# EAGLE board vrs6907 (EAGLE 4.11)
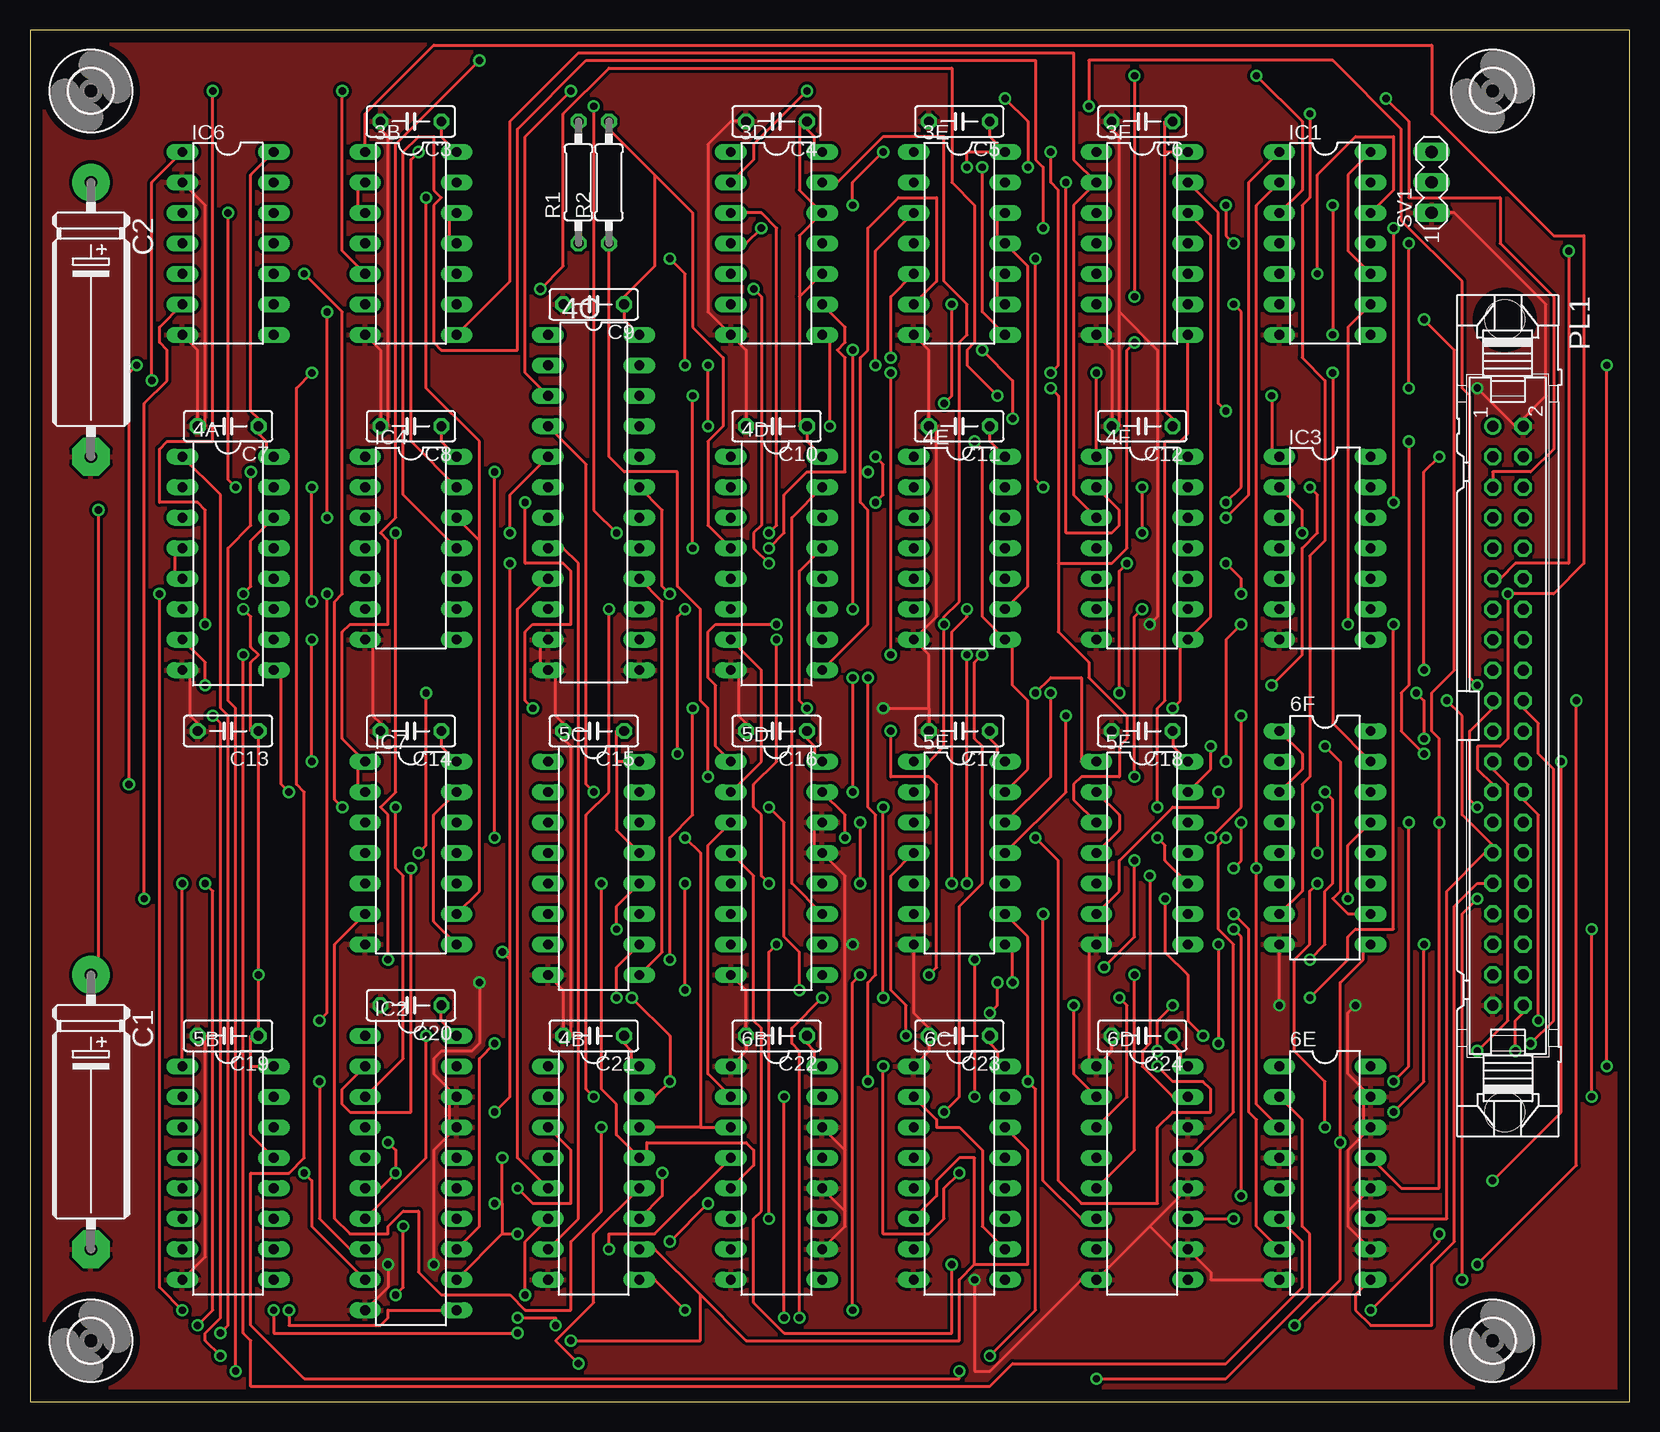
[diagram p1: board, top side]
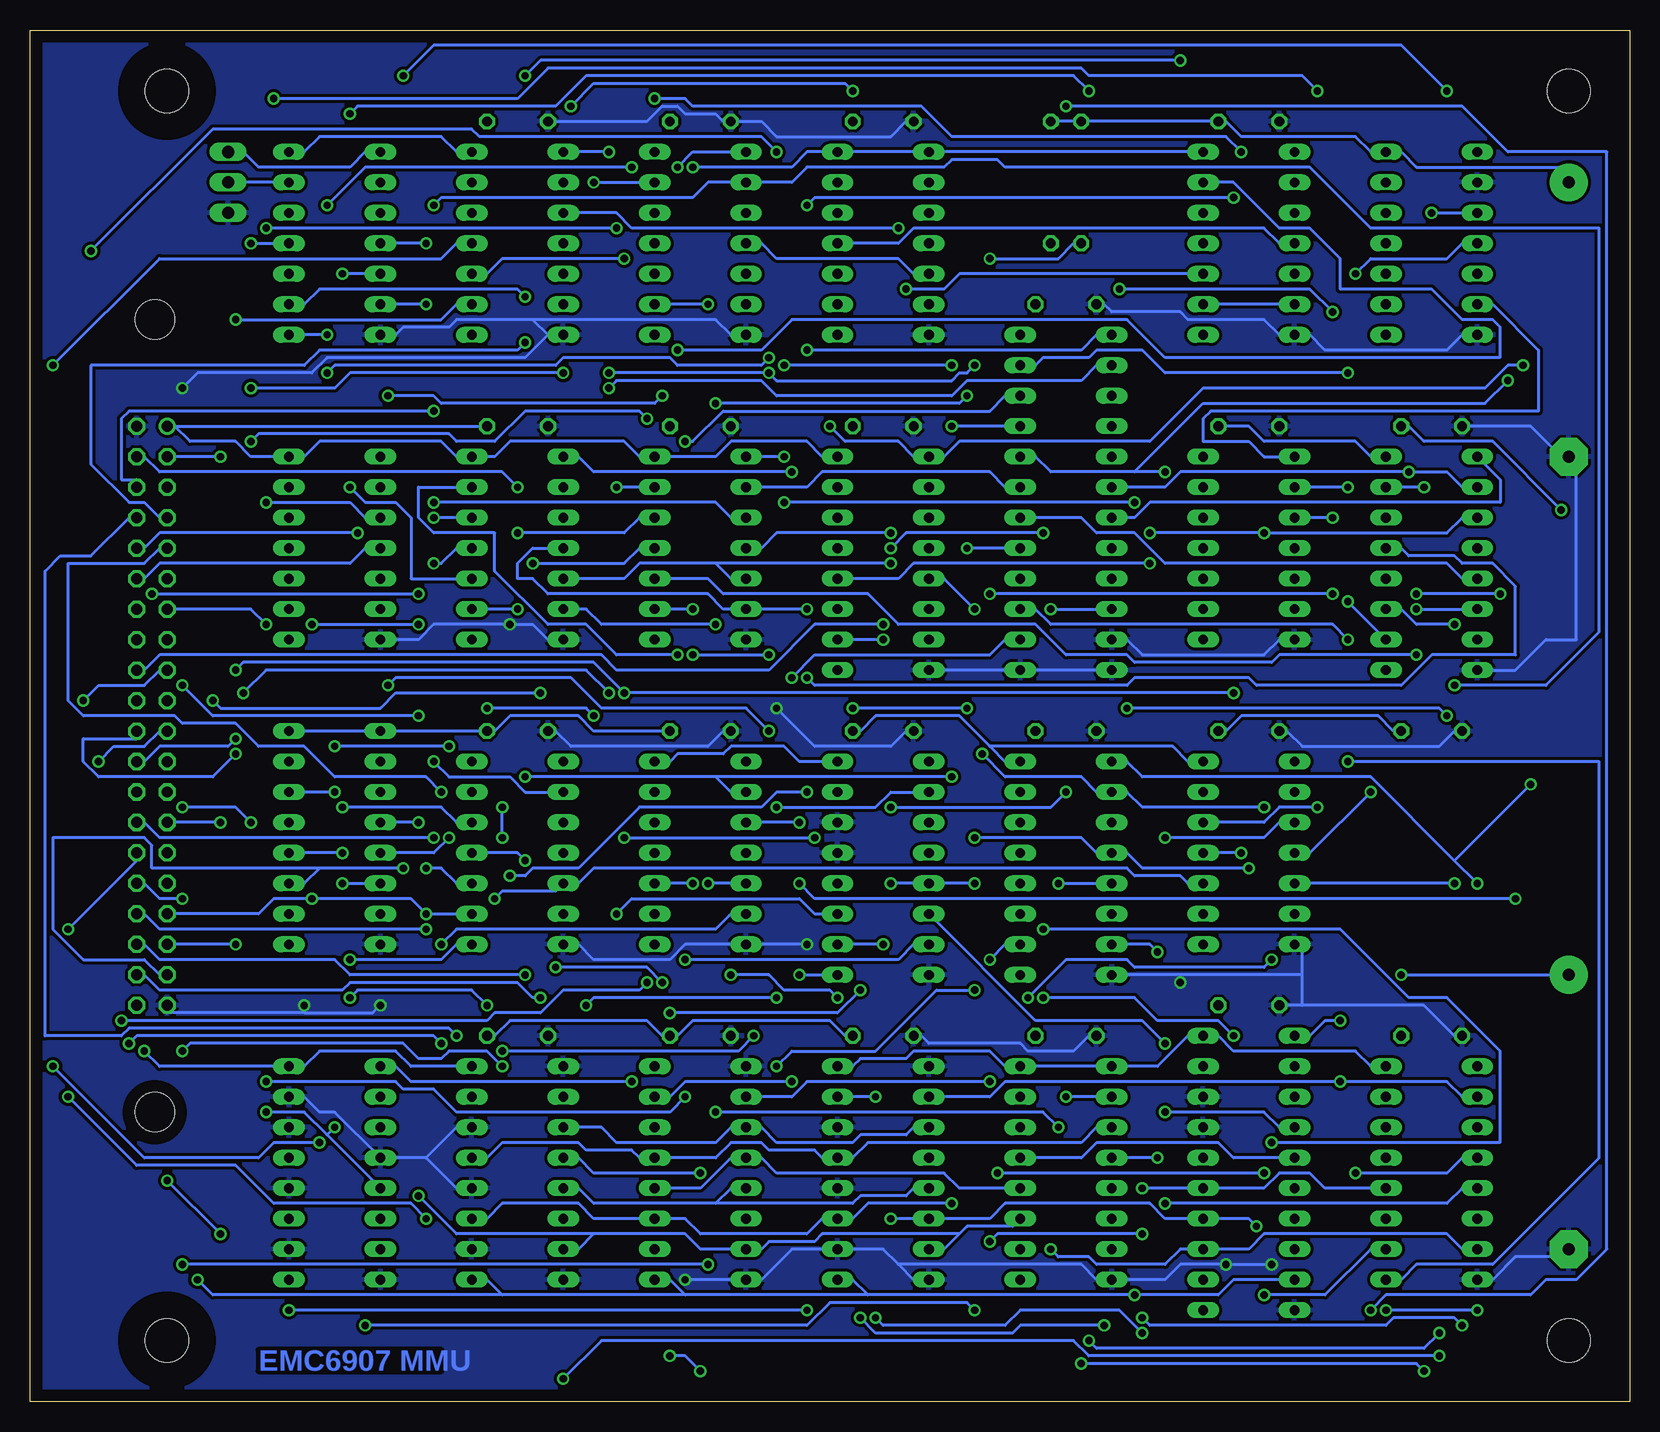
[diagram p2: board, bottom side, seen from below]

Size 133.35 x 114.3 mm. Coordinates in mm from the lower left corner, seen from the top.
Outline: 0,0 133.35,0 133.35,114.3 0,114.3 0,0
Copper layers (1*16): Top 0.035mm / dielectric 1.5mm / Bottom 0.035mm
Design rules "10mils": minimum track width 10mil, minimum drill 24mil, track to track 10mil, track to pad 10mil, pad to pad 10mil, via to via 10mil, smd to smd 10mil, copper to edge 40mil, drill to drill 10mil, minimum pad ring 10mil, minimum via ring 8mil, stop-mask expansion 0mil, vias tented up to drill 0mil, thermal gap 10mil

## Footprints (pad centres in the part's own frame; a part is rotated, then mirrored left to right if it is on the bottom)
DIL14 = drill 0.813 long: 1 -7.62,-3.81; 2 -5.08,-3.81; 3 -2.54,-3.81; 4 0,-3.81; 5 2.54,-3.81; 6 5.08,-3.81; 7 7.62,-3.81; 8 7.62,3.81; 9 5.08,3.81; 10 2.54,3.81; 11 0,3.81; 12 -2.54,3.81; 13 -5.08,3.81; 14 -7.62,3.81
DIL16 = drill 0.813 long: 1 -8.89,-3.81; 2 -6.35,-3.81; 3 -3.81,-3.81; 4 -1.27,-3.81; 5 1.27,-3.81; 6 3.81,-3.81; 7 6.35,-3.81; 8 8.89,-3.81; 9 8.89,3.81; 10 6.35,3.81; 11 3.81,3.81; 12 1.27,3.81; 13 -1.27,3.81; 14 -3.81,3.81; 15 -6.35,3.81; 16 -8.89,3.81
DIL24-3 = drill 0.813 long: 1 -13.97,-3.81; 2 -11.43,-3.81; 3 -8.89,-3.81; 4 -6.35,-3.81; 5 -3.81,-3.81; 6 -1.27,-3.81; 7 1.27,-3.81; 8 3.81,-3.81; 9 6.35,-3.81; 10 8.89,-3.81; 11 11.43,-3.81; 12 13.97,-3.81; 13 13.97,3.81; 14 11.43,3.81; 15 8.89,3.81; 16 6.35,3.81; 17 3.81,3.81; 18 1.27,3.81; 19 -1.27,3.81; 20 -3.81,3.81; 21 -6.35,3.81; 22 -8.89,3.81; 23 -11.43,3.81; 24 -13.97,3.81
E22-6 = drill 1.016 pad 3.15 round: + -11.43,0 | drill 1.016 pad 3.15 octagon: - 11.43,0
C050-025X075 = drill 0.813 octagon: 1 -2.54,0; 2 2.54,0
DIL20 = drill 0.813 long: 1 -11.43,-3.81; 2 -8.89,-3.81; 3 -6.35,-3.81; 4 -3.81,-3.81; 5 -1.27,-3.81; 6 1.27,-3.81; 7 3.81,-3.81; 8 6.35,-3.81; 9 8.89,-3.81; 10 11.43,-3.81; 11 11.43,3.81; 12 8.89,3.81; 13 6.35,3.81; 14 3.81,3.81; 15 1.27,3.81; 16 -1.27,3.81; 17 -3.81,3.81; 18 -6.35,3.81; 19 -8.89,3.81; 20 -11.43,3.81
40V = drill 0.914 round: 1 -24.13,-1.27 | drill 0.914 octagon: 2 -24.13,1.27; 3 -21.59,-1.27; 4 -21.59,1.27; 5 -19.05,-1.27; 6 -19.05,1.27; 7 -16.51,-1.27; 8 -16.51,1.27; 9 -13.97,-1.27; 10 -13.97,1.27; 11 -11.43,-1.27; 12 -11.43,1.27; 13 -8.89,-1.27; 14 -8.89,1.27; 15 -6.35,-1.27; 16 -6.35,1.27; 17 -3.81,-1.27; 18 -3.81,1.27; 19 -1.27,-1.27; 20 -1.27,1.27; 21 1.27,-1.27; 22 1.27,1.27; 23 3.81,-1.27; 24 3.81,1.27; 25 6.35,-1.27; 26 6.35,1.27; 27 8.89,-1.27; 28 8.89,1.27; 29 11.43,-1.27; 30 11.43,1.27; 31 13.97,-1.27; 32 13.97,1.27; 33 16.51,-1.27; 34 16.51,1.27; 35 19.05,-1.27; 36 19.05,1.27; 37 21.59,-1.27; 38 21.59,1.27; 39 24.13,-1.27; 40 24.13,1.27 | hole 3.302: 33.02,-0.254; -33.02,-0.254
0207/10 = drill 0.813 octagon: 1 -5.08,0; 2 5.08,0
MA03-1 = drill 1.016 long: 1 -2.54,0; 2 0,0; 3 2.54,0
3,6 = hole 3.6: 0,0

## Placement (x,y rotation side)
3B  7414N  [DIL14]  31.75,96.52 270 top
3D  74LS74N  [DIL14]  62.23,96.52 270 top
3E  74LS10N  [DIL14]  77.47,96.52 270 top
3F  74LS00N  [DIL14]  92.71,96.52 270 top
4A  74HCT138N  [DIL16]  16.51,69.85 270 top
4B  74LS174N  [DIL16]  46.99,19.05 270 top
4C  20L10  [DIL24-3]  46.99,74.93 270 top
4D  74LS175N  [DIL16]  62.23,69.85 270 top
4E  74LS02N  [DIL14]  77.47,71.12 270 top
4F  74LS04N  [DIL14]  92.71,71.12 270 top
5B  74LS175N  [DIL16]  16.51,19.05 270 top
5C  74LS175N  [DIL16]  46.99,44.45 270 top
5D  74LS257N  [DIL16]  62.23,44.45 270 top
5E  7407N  [DIL14]  77.47,45.72 270 top
5F  74LS32N  [DIL14]  92.71,45.72 270 top
6B  74LS365N  [DIL16]  62.23,19.05 270 top
6C  74LS365N  [DIL16]  77.47,19.05 270 top
6D  74LS365N  [DIL16]  92.71,19.05 270 top
6E  74LS365N  [DIL16]  107.95,19.05 270 top
6F  74LS174N  [DIL16]  107.95,46.99 270 top
C1  27uf  [E22-6]  5.08,24.13 270 top
C2  27uf  [E22-6]  5.08,90.17 270 top
C3  .01uf  [C050-025X075]  31.75,106.68 180 top
C4  .01uf  [C050-025X075]  62.23,106.68 180 top
C5  .01uf  [C050-025X075]  77.47,106.68 180 top
C6  .01uf  [C050-025X075]  92.71,106.68 180 top
C7  .01uf  [C050-025X075]  16.51,81.28 180 top
C8  .01uf  [C050-025X075]  31.75,81.28 180 top
C9  .01uf  [C050-025X075]  46.99,91.44 180 top
C10  .01uf  [C050-025X075]  62.23,81.28 180 top
C11  .01uf  [C050-025X075]  77.47,81.28 180 top
C12  .01uf  [C050-025X075]  92.71,81.28 180 top
C13  .01uf  [C050-025X075]  16.51,55.88 180 top
C14  .01uf  [C050-025X075]  31.75,55.88 180 top
C15  .01uf  [C050-025X075]  46.99,55.88 180 top
C16  .01uf  [C050-025X075]  62.23,55.88 180 top
C17  .01uf  [C050-025X075]  77.47,55.88 180 top
C18  .01uf  [C050-025X075]  92.71,55.88 180 top
C19  .01uf  [C050-025X075]  16.51,30.48 180 top
C20  .01uf  [C050-025X075]  31.75,33.02 180 top
C21  .01uf  [C050-025X075]  46.99,30.48 180 top
C22  .01uf  [C050-025X075]  62.23,30.48 180 top
C23  .01uf  [C050-025X075]  77.47,30.48 180 top
C24  .01uf  [C050-025X075]  92.71,30.48 180 top
IC1  74LS74N  [DIL14]  107.95,96.52 270 top
IC2  74HCT374N  [DIL20]  31.75,19.05 270 top
IC3  7407N  [DIL14]  107.95,71.12 270 top
IC4  74LS32N  [DIL14]  31.75,71.12 270 top
IC6  74LS74N  [DIL14]  16.51,96.52 270 top
IC7  74LS10N  [DIL14]  31.75,45.72 270 top
PL1  [40V]  123.19,57.15 270 top
R1  [0207/10]  45.72,101.6 90 top
R2  [0207/10]  48.26,101.6 90 top
SV1  [MA03-1]  116.84,101.6 90 top
U$1  [3,6]  5.08,109.22 0 top
U$2  [3,6]  121.92,109.22 0 top
U$3  [3,6]  5.08,5.08 0 top
U$4  [3,6]  121.92,5.08 0 top

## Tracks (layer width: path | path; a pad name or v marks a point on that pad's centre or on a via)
2X4\
  Top 0.254: 4A.5 12.06,69.22 12.06,70.48 4A.4
  Bottom 0.254: 4C.18 45.72,73.66 44.45,72.39 41.27,72.39 38.73,69.85 15.24,69.85 13.97,68.58 4A.5
ANYJ  (via drill 0.61)
  Top 0.254: v98.42,46.99 100.97,49.53 v100.97,57.15 | v120.65,59.69 120.02,60.33 120.02,83.82 119.38,84.45 119.38,93.34 114.3,98.42 114.3,106.05 108.58,111.76 88.27,111.76 v88.27,107.95 | v64.77,109.22 60.33,104.78 60.33,103.5 3D.2
  Bottom 0.254: v98.42,46.99 99.69,45.72 6F.5 | v100.97,57.15 118.11,57.15 v120.65,59.69 | v88.27,107.95 86.36,109.86 65.41,109.86 v64.77,109.22
C0\  (via drill 0.61)
  Top 0.254: v85.09,59.05 85.09,52.07 5E.12 | v115.57,59.05 116.2,58.42 v116.2,55.24
  Bottom 0.254: v85.09,59.05 87,60.96 113.67,60.96 v115.57,59.05 | v116.2,55.24 116.84,54.61 122.56,54.61 123.83,53.34 PL1.24
C1\  (via drill 0.61)
  Top 0.254: v81.92,34.92 81.92,37.47 5E.8 | v125.73,31.75 125.73,48.9 124.46,50.16 PL1.26
  Bottom 0.254: v81.92,34.92 82.55,34.29 88.9,34.29 90.81,32.38 94.61,32.38 95.25,31.75 v125.73,31.75
CINT\  (via drill 0.61)
  Top 0.254: v17.14,76.2 16.51,76.83 v16.51,99.06
  Bottom 0.254: v17.14,76.2 4A.15 | v16.51,99.06 IC6.3
CLKDF  (via drill 0.61)
  Top 0.254: v23.5,53.34 v23.5,63.5
  Bottom 0.254: v23.5,53.34 2.54,53.34 2.54,20.32 11.43,11.43 17.78,11.43 19.05,10.16 5B.9 | v23.5,63.5 24.77,64.77 48.26,64.77 49.53,66.04 4C.15
CLKIB
  Top 0.254: 5C.9 52.7,37.47 52.7,66.67 4C.16
CLKIF  (via drill 0.61)
  Top 0.254: v56.52,81.28 v56.52,86.36 | v70.48,86.36 70.48,95.89 3E.3
  Bottom 0.254: v56.52,86.36 v70.48,86.36 | 4C.21 v56.52,81.28
CPUDEVSEL\  (via drill 0.61)
  Top 0.254: v32.38,45.72 33.02,46.35 v33.02,59.05 | v83.82,59.05 85.09,60.33 87.63,60.33 87.63,53.34 5F.1 | v117.47,78.74 116.2,77.47 v116.2,60.96
  Bottom 0.254: v33.02,59.05 v83.82,59.05 86.36,61.59 115.57,61.59 v116.2,60.96 | v32.38,45.72 IC7.11 | v117.47,78.74 PL1.3
CPUSWSEL\  (via drill 0.61)
  Top 0.254: v97.79,30.48 96.52,31.75 96.52,35.56 94.61,37.47 v94.61,41.91
  Bottom 0.254: IC7.10 36.83,43.18 37.47,43.81 41.27,43.81 41.91,44.45 86.36,44.45 87.63,43.18 5F.5 89.53,42.55 93.98,42.55 v94.61,41.91 | v97.79,30.48 98.42,31.11 125.09,31.11 125.73,30.48 132.08,30.48 132.08,69.22 130.81,70.48 128.27,70.48 125.09,73.66 PL1.8
CUF\  (via drill 0.61)
  Top 0.254: v21.59,50.8 20.95,51.44 20.95,60.33 4A.9
  Bottom 0.254: v21.59,50.8 26.67,45.72 IC7.4
DATAF  (via drill 0.61)
  Top 0.254: v62.23,64.77 57.15,64.77 56.52,64.14 56.52,60.33 57.15,59.69 57.15,54.61 5D.1
  Bottom 0.254: v62.23,64.77 67.94,64.77 71.75,60.96 84.45,60.96 85.72,62.23 122.56,62.23 123.83,60.96 PL1.18
DEVSEL\  (via drill 0.61)
  Top 0.254: 85.72,69.85 85.72,83.82 v85.09,84.45 | 85.72,69.85 85.72,64.14 88.27,61.59 88.27,60.33 91.44,57.15 91.44,55.24 90.81,54.61 90.81,52.07 87.63,52.07 87,51.44 87,50.16 5F.3 | v92.08,88.27 91.44,87.63 91.44,71.12 90.17,69.85 85.72,69.85
  Bottom 0.254: v85.09,84.45 84.45,85.09 72.39,85.09 71.12,83.82 56.52,83.82 55.24,85.09 45.72,85.09 44.45,86.36 4C.2 | v92.08,88.27 92.71,87.63 109.22,87.63 110.49,86.36 128.27,86.36 128.27,78.11 125.09,74.93 123.83,74.93 122.56,73.66 PL1.7
DIRJ  (via drill 0.61)
  Top 0.254: v108.58,85.72 108.58,56.52 6F.15 | v71.75,87 71.75,92.08 3E.5
  Bottom 0.254: v108.58,85.72 107.95,86.36 89.53,86.36 88.9,87 80.01,87 79.38,86.36 72.39,86.36 v71.75,87
DMAGNT  (via drill 0.61)
  Top 0.254: v67.94,46.99 67.94,48.9 5D.15 | v83.82,46.99 85.72,45.09 85.72,18.41 87.63,16.51 93.98,16.51 93.98,22.86 95.25,24.13 98.42,24.13 98.42,26.04 97.79,26.67 95.25,26.67 v93.98,27.94 | v120.65,29.21 123.19,31.75 123.19,51.44 121.92,52.7 PL1.23
  Bottom 0.254: v83.82,46.99 v67.94,46.99 | v93.98,27.94 95.25,29.21 98.42,29.21 99.06,28.57 100.97,28.57 102.23,29.84 120.02,29.84 v120.65,29.21
DX0  (via drill 0.61)
  Top 0.254: 6E.13 114.3,17.78 117.47,17.78 v117.47,48.26 117.47,55.24 116.84,55.88 116.84,59.05 118.75,60.96 118.75,87.63 v116.2,90.17
  Bottom 0.254: v117.47,48.26 PL1.27 | v116.2,90.17 99.06,90.17 97.79,91.44 3F.9
DX1  (via drill 0.61)
  Top 0.254: v91.44,69.85 90.81,69.22 v90.81,59.05 | v118.11,58.42 119.38,57.15 119.38,48.9 121.92,46.35 PL1.29 121.28,45.72 118.11,42.55 118.11,15.24 6E.11
  Bottom 0.254: v91.44,69.85 83.82,69.85 82.55,71.12 4E.11 | v90.81,59.05 102.87,59.05 104.14,57.78 117.47,57.78 v118.11,58.42
DX2
  Top 0.254: 6E.9 110.49,8.89 110.49,7.62 111.76,6.35 116.84,6.35 116.84,11.43 118.75,13.34 118.75,41.27 120.65,43.18 PL1.31
DX3  (via drill 0.61)
  Top 0.254: v100.33,40.64 101.6,39.37 101.6,24.13 102.23,23.5 102.23,14.61 6E.7 | v109.86,41.91 109.86,46.35 6F.13
  Bottom 0.254: 5F.9 v100.33,40.64 101.6,41.91 v109.86,41.91 113.03,41.91 114.3,40.64 PL1.33
DX4  (via drill 0.61)
  Top 0.254: v113.67,24.13 116.2,26.67 v116.2,38.1 | v107.31,43.18 106.68,42.55 106.68,38.1 105.41,36.83 105.41,29.21 107.95,26.67 v107.95,22.86
  Bottom 0.254: 108.58,22.23 110.49,24.13 v113.67,24.13 | 6E.5 108.58,22.23 | v116.2,38.1 PL1.35 | 108.58,22.23 v107.95,22.86 | v107.31,43.18 6F.6
DX5  (via drill 0.61)
  Top 0.254: 6E.3 102.23,24.77 v102.23,44.45 102.23,99.69 IC1.2
  Bottom 0.254: 109.22,44.45 110.49,43.18 6F.11 | v102.23,44.45 109.22,44.45 | 109.22,44.45 123.19,44.45 123.19,46.35 123.83,46.99 131.44,46.99 131.44,39.37 128.91,36.83 123.83,36.83 122.56,35.56 PL1.37
DX6  (via drill 0.61)
  Top 0.254: v31.75,44.45 31.75,24.13 26.67,24.13 26.04,24.77 26.04,26.04 IC2.2 | 55.88,22.86 4B.14 | 55.88,22.86 6B.3 | v90.81,33.66 91.44,33.02 91.44,25.4 6D.3 | v54.61,46.99 55.88,45.72 55.88,22.86
  Bottom 0.254: v31.75,44.45 40.64,44.45 41.91,45.72 5C.4 44.45,45.72 45.72,46.99 v54.61,46.99 | 6D.3 85.72,22.86 84.45,21.59 76.2,21.59 74.93,22.86 6C.3 72.39,22.86 71.12,21.59 64.77,21.59 64.14,22.23 60.33,22.23 59.69,22.86 6B.3 | v90.81,33.66 91.44,33.66 92.71,34.92 106.68,34.92 107.31,34.29 122.56,34.29 123.83,35.56 PL1.38
DX7  (via drill 0.61)
  Top 0.254: 6B.5 60.33,19.68 60.33,20.95 59.69,21.59 51.44,21.59 51.44,20.95 4B.13 48.9,22.23 48.9,24.77 47.62,26.04 v47.62,43.18 | v92.08,35.56 92.08,20.95 6D.5
  Bottom 0.254: IC2.5 33.02,20.32 34.29,21.59 44.45,21.59 45.72,20.32 4B.13 | v47.62,43.18 5C.5 | 76.2,16.51 74.93,17.78 6C.5 | 76.2,16.51 86.36,16.51 87.63,17.78 6D.5 | v92.08,35.56 106.68,35.56 107.95,36.83 122.56,36.83 123.83,38.1 PL1.36 | 76.2,16.51 64.77,16.51 64.14,17.14 60.33,17.14 59.69,17.78 6B.5
DX8  (via drill 0.61)
  Top 0.254: v52.7,19.05 52.7,17.14 4B.11 | IC2.6 29.21,17.78 v30.48,19.05 30.48,20.95 v29.84,21.59 | v48.9,39.37 48.9,41.27 5C.12 | v100.33,39.37 100.97,38.73 v100.97,17.14
  Bottom 0.254: 55.88,13.97 55.24,14.61 51.44,14.61 4B.11 | 55.88,13.97 57.15,12.7 6B.7 | 55.88,13.97 67.31,13.97 67.94,13.34 71.75,13.34 72.39,12.7 6C.7 77.47,12.7 78.74,13.97 86.36,13.97 | v30.48,19.05 v52.7,19.05 | v48.9,39.37 24.13,39.37 18.41,33.66 15.24,33.66 10.79,29.21 10.79,21.59 v29.84,21.59 | 86.36,13.97 87.63,12.7 6D.7 | v100.33,39.37 122.56,39.37 123.83,40.64 PL1.34 | v100.97,17.14 97.79,13.97 86.36,13.97
DX9  (via drill 0.61)
  Top 0.254: v41.27,8.89 41.27,13.34 4B.6 | v22.86,19.05 23.5,18.41 23.5,14.61 IC2.9 | v120.65,41.91 119.38,40.64 v119.38,10.16
  Bottom 0.254: 63.5,8.89 v41.27,8.89 34.29,8.89 33.02,10.16 IC2.9 | 63.5,8.89 64.77,10.16 6B.9 | 78.74,8.89 80.01,10.16 6C.9 | 63.5,8.89 78.74,8.89 | v22.86,19.05 15.24,19.05 13.97,20.32 5B.4 | 93.98,8.89 95.25,10.16 6D.9 | 78.74,8.89 93.98,8.89 | v120.65,41.91 122.56,41.91 123.83,43.18 PL1.32 | v119.38,10.16 118.11,8.89 93.98,8.89
DX10  (via drill 0.61)
  Top 0.254: 39.37,16.51 v39.37,20.32 | 39.37,16.51 39.37,13.97 | 39.37,13.97 IC2.12 | v38.73,16.51 39.37,16.51 | v130.18,25.4 v130.18,39.37 | 6D.11 v100.33,15.24 | 39.37,13.97 v40.64,13.97 | v53.34,13.34 v56.52,16.51
  Bottom 0.254: v39.37,20.32 4B.4 | v38.73,16.51 15.24,16.51 13.97,17.78 5B.5 | 6D.11 95.25,15.24 93.98,16.51 87.63,16.51 86.36,15.24 6C.11 78.74,15.24 77.47,13.97 68.58,13.97 67.31,15.24 6B.11 64.77,15.24 63.5,16.51 v56.52,16.51 | v130.18,39.37 124.46,45.09 PL1.30 | v130.18,25.4 124.46,19.68 116.2,19.68 113.03,16.51 101.6,16.51 v100.33,15.24 | v40.64,13.97 52.7,13.97 v53.34,13.34
DX11  (via drill 0.61)
  Top 0.254: v40.64,17.78 41.91,16.51 45.09,16.51 45.09,20.95 4B.3 | v99.69,46.99 99.06,46.35 99.06,39.37 100.33,38.1 100.33,24.13 6D.13
  Bottom 0.254: 5B.12 25.4,17.78 26.67,19.05 29.21,19.05 30.48,17.78 IC2.15 v40.64,17.78 | 4B.3 44.45,22.86 45.72,21.59 63.5,21.59 64.77,20.32 6B.13 67.31,20.32 67.94,20.95 71.75,20.95 72.39,21.59 74.93,21.59 76.2,20.32 6C.13 82.55,20.32 83.19,20.95 87,20.95 87.63,21.59 93.98,21.59 95.25,20.32 6D.13 | v99.69,46.99 122.56,46.99 123.83,48.26 PL1.28
EM0  (via drill 0.61)
  Top 0.254: v76.83,11.43 76.83,5.71 62.87,5.71 60.33,8.26 60.33,15.24 60.96,15.88 60.96,31.11 60.33,31.75 60.33,43.81 5D.4 | v120.65,11.43 128.91,19.68 v128.91,58.42
  Bottom 0.254: v76.83,11.43 v120.65,11.43 | v128.91,58.42 127.64,59.69 123.83,59.69 122.56,60.96 PL1.17
EM1  (via drill 0.61)
  Top 0.254: v78.74,36.83 v78.74,25.4 | v113.67,26.67 114.94,27.94 v114.94,48.26 | v120.65,49.53 120.02,50.16 120.02,55.88 121.92,57.78 PL1.19
  Bottom 0.254: v78.74,36.83 60.96,36.83 59.69,38.1 5D.7 | v78.74,25.4 80.01,24.13 97.79,24.13 99.69,26.04 102.23,26.04 102.87,26.67 v113.67,26.67 | v114.94,48.26 116.2,49.53 v120.65,49.53
EM2  (via drill 0.61)
  Top 0.254: v69.22,35.56 68.58,34.92 v68.58,7.62 | v111.76,7.62 117.47,13.34 v117.47,13.97 | v121.92,18.41 127.64,24.13 v127.64,53.34
  Bottom 0.254: v68.58,7.62 v111.76,7.62 | v117.47,13.97 v121.92,18.41 | v127.64,53.34 126.36,54.61 123.83,54.61 122.56,55.88 PL1.21 | v69.22,35.56 5D.9
ENSF\  (via drill 0.61)
  Top 0.254: v24.13,31.75 24.77,32.38 v24.77,67.31 | v53.34,67.31 52.7,67.94 52.7,74.3 4C.19
  Bottom 0.254: v24.13,31.75 25.4,31.75 26.67,30.48 IC2.1 | v24.77,67.31 v53.34,67.31 | 4E.2 68.58,76.2 67.31,77.47 53.34,77.47 52.07,76.2 4C.19
ERROR\  (via drill 0.61)
  Top 0.254: v26.04,49.53 25.4,50.16 25.4,66.67 26.04,67.31 26.04,90.81 v22.86,93.98
  Bottom 0.254: v26.04,49.53 29.21,49.53 30.48,48.26 IC7.12 | v22.86,93.98 21.59,95.25 15.24,95.25 13.97,96.52 IC6.4
GND  (via drill 0.61)
  Top 0.254: v104.14,33.02 6F.8 | 109.86,15.88 109.86,14.61 6E.10 | 109.86,15.88 6E.12 | 109.86,15.88 109.86,20.95 6E.14 111.12,23.5 111.12,24.77 6E.15 109.86,27.3 109.86,32.38 v110.49,33.02 | 93.34,14.61 6D.8 87.63,10.16 80.01,2.54 78.74,2.54 v78.74,10.16 | 93.34,14.61 6D.12 | 93.34,14.61 95.25,12.7 6D.10 98.42,10.79 98.42,10.16 6E.8 | v29.84,11.43 29.84,9.53 IC2.10 | v33.66,11.43 33.66,20.95 IC2.17 34.92,23.5 34.92,24.77 IC2.18 33.66,27.3 33.66,28.57 34.29,29.21 36.83,29.21 37.47,29.84 v37.47,34.92 | 6C.1 74.93,29.21 C23.2 74.93,31.11 73.66,32.38 5E.7 | C24.2 90.17,29.21 6D.1 88.27,28.57 88.27,37.47 5F.7 | 5D.14 65.41,47.62 65.41,46.35 5D.13 67.94,43.81 67.94,38.1 | 67.94,15.88 67.94,14.61 6B.10 | 67.94,15.88 6B.12 | 67.94,15.88 67.94,20.95 | 67.94,20.95 6B.14 | 67.94,20.95 67.94,38.1 | 67.94,38.1 v68.58,38.1 | C10.2 59.69,87.63 3D.7 56.52,90.81 56.52,104.78 58.42,106.68 C4.2 | SV1.1 118.75,99.06 126.36,91.44 126.36,83.82 124.46,81.92 PL1.2 123.83,81.28 v120.65,84.45 | 74.93,57.78 74.93,62.23 4E.7 75.56,65.41 75.56,81.28 C11.2 74.93,87.63 3E.7 | 74.93,57.78 C17.2 | 3F.7 90.17,87.63 C12.2 90.81,81.28 90.81,90.81 | 90.81,90.81 90.81,105.41 90.17,106.05 C6.2 | v93.34,64.77 93.98,65.41 93.98,87.63 90.81,90.81 | IC6.7 13.97,87.63 C7.2 14.61,81.28 14.61,99.69 IC6.2 | 3B.7 29.21,87.63 C8.2 29.84,81.28 29.84,105.41 29.21,106.05 C3.2 | C13.2 13.97,56.52 13.34,57.15 13.34,60.33 4A.8 | C14.2 29.21,56.52 28.57,57.15 28.57,62.87 IC4.7 | C16.2 59.69,56.52 59.05,57.15 59.05,60.33 4D.8 | 4C.11 42.55,62.87 42.55,61.59 4C.12 43.81,60.33 43.81,57.15 44.45,56.52 C15.2 44.45,55.24 45.09,54.61 45.09,30.48 C21.2 44.45,34.29 5C.8
  Top 0.254: 6B.1 59.69,29.21 C22.2 59.69,34.29 5D.8 | 5B.8 14.61,12.06 14.61,30.48 C19.2 | v71.12,57.78 74.93,57.78
  Bottom 0.254: v104.14,33.02 104.78,32.38 110.49,32.38 | 110.49,32.38 121.92,32.38 PL1.39 | 100.33,20.32 97.79,22.86 6D.14 | 100.33,20.32 6E.4 107.95,24.13 109.22,24.13 110.49,25.4 6E.15 | 100.33,20.32 97.79,17.78 6D.12 | v110.49,33.02 110.49,32.38 | v29.84,11.43 v33.66,11.43 37.47,11.43 38.73,10.16 4B.8 44.45,10.16 45.72,11.43 60.96,11.43 | 5F.7 87.63,38.1 86.36,36.83 80.01,36.83 78.74,38.1 5E.7 v68.58,38.1 | 60.96,11.43 62.23,12.7 6B.10 69.85,12.7 72.39,10.16 6C.8 v78.74,10.16 | 60.96,11.43 59.69,10.16 6B.8 | C4.2 60.33,106.68 61.59,105.41 71.12,105.41 72.39,106.68 C5.2 75.56,106.68 76.2,107.31 78.74,107.31 79.38,107.95 80.64,107.95 81.92,106.68 C6.2 | C18.2 89.53,55.88 88.27,54.61 76.83,54.61 75.56,55.88 C17.2 | 4F.7 90.17,63.5 91.44,64.77 v93.34,64.77 99.69,64.77 100.97,63.5 IC3.7 | 91.44,90.17 97.79,90.17 98.42,89.53 102.23,89.53 102.87,88.9 IC1.7 | 91.44,90.17 90.17,88.9 | 91.44,90.17 76.2,90.17 74.93,88.9 3E.7 | v120.65,84.45 119.38,85.72 109.86,85.72 108.58,87 92.08,87 90.17,88.9 | 90.17,88.9 3F.7 | C7.2 8.26,81.28 6.35,79.38 C2.- 4.45,77.47 4.45,63.5 6.99,63.5 9.53,60.96 4A.8 | C9.2 43.81,91.44 43.18,90.81 37.47,90.81 36.83,90.17 30.48,90.17 29.21,88.9 3B.7 26.67,88.9 25.4,87.63 15.24,87.63 13.97,88.9 IC6.7 | C13.2 14.61,55.88 15.88,54.61 27.3,54.61 28.57,55.88 C14.2 | 4C.12 4C.13 4D.8 | IC4.7 29.21,63.5 30.48,62.23 40.64,62.23 41.91,63.5 4C.11 | 5B.8 11.43,10.16 9.53,12.06 6.35,12.06 C1.- | 27.3,33.02 17.14,33.02 14.61,30.48 C19.2 | 27.3,33.02 C20.2 | 27.3,33.02 27.3,35.56 | 27.3,35.56 27.3,37.47 IC7.7 | 27.3,35.56 37.47,35.56 | 37.47,35.56 5C.8 | C22.2 59.05,30.48 58.42,29.84 50.8,29.84 50.16,29.21 46.35,29.21 45.09,30.48 C21.2
  Bottom 0.254: v71.12,57.78 67.94,54.61 61.59,54.61 60.33,55.88 C16.2 | 37.47,35.56 v37.47,34.92
  pour Bottom: 0,0 0,114.3 133.35,114.3 133.35,0
  pour Top: 0,0 0,114.3 133.35,114.3 133.35,0
GTF\  (via drill 0.61)
  Top 0.254: 5E.13 83.19,52.7 83.19,58.42 81.92,59.69 81.92,62.87 4E.8 79.38,65.41 79.38,79.38 v78.74,80.01
  Bottom 0.254: v78.74,80.01 78.11,80.01 75.56,82.55 53.34,82.55 52.07,83.82 4C.22
IFETCH  (via drill 0.61)
  Top 0.254: v79.38,87.63 81.92,85.09 v81.92,81.92 | v114.94,80.01 114.94,59.69 114.3,59.05 114.3,55.88 v116.2,53.98
  Bottom 0.254: v79.38,87.63 72.39,87.63 69.85,90.17 41.91,90.17 38.73,87 10.79,87 10.79,89.53 11.43,90.17 13.97,90.17 16.51,92.71 24.13,92.71 24.13,95.25 26.67,97.79 29.21,97.79 33.02,101.6 3B.13 | v81.92,81.92 82.55,82.55 92.08,82.55 94.61,80.01 97.79,80.01 98.42,80.64 114.3,80.64 v114.94,80.01 | v116.2,53.98 118.11,52.07 127.64,52.07 128.91,53.34 128.91,55.24 124.46,55.24 PL1.22
INHIBIT\  (via drill 0.61)
  Top 0.254: 3E.12 80.64,98.42 80.64,97.16 3E.11 83.19,94.61 83.19,67.94 4E.9 | v76.83,43.18 76.83,64.14 78.11,65.41 v78.11,66.04
  Bottom 0.254: 5E.5 v76.83,43.18 | v78.11,66.04 4E.9
INHSET\  (via drill 0.61)
  Top 0.254: v55.24,71.12 v55.24,83.82 | v76.2,83.19 76.83,83.82 v76.83,91.44 | 3E.10 80.64,93.34 80.64,92.08 3E.9
  Bottom 0.254: v55.24,83.82 55.88,83.19 v76.2,83.19 | 4C.17 v55.24,71.12 | v76.83,91.44 3E.9
INTDIS  (via drill 0.61)
  Top 0.254: v99.06,38.1 v99.06,29.84 | v125.09,29.84 127,31.75 127,52.7 125.73,53.98 125.73,56.52 124.46,57.78 PL1.20
  Bottom 0.254: v99.06,38.1 97.79,39.37 76.2,39.37 74.93,40.64 5E.6 | v99.06,29.84 99.69,30.48 124.46,30.48 v125.09,29.84
INTGNT  (via drill 0.61)
  Top 0.254: v99.69,69.85 100.97,68.58 v100.97,67.31 | PL1.25 121.92,51.44 120.65,52.7 120.65,54.61 122.56,54.61 123.19,55.24 v123.19,67.31 127,67.31 129.54,69.85 129.54,97.16 127,97.16 116.84,107.31 116.84,113.03 33.66,113.03 27.94,107.31 3B.1
  Bottom 0.254: v99.69,69.85 99.06,69.85 97.79,71.12 4F.11 | v123.19,67.31 v100.97,67.31
INTGNT\  (via drill 0.61)
  Top 0.254: v14.61,43.18 15.24,42.55 15.24,7.62 v13.97,6.35 | v40.64,6.99 43.81,6.99 v43.81,6.35 | v64.14,6.99 64.14,29.21 63.5,29.84 63.5,31.11 v66.04,33.66 | v74.93,35.56 75.56,36.2 75.56,51.44 74.93,52.07 71.75,52.07 v71.75,55.88 | v103.5,59.69 106.05,62.23 106.05,71.12 107.31,72.39 107.31,75.56 v106.68,76.2
  Bottom 0.254: v13.97,6.35 14.61,6.99 19.68,6.99 20.32,6.35 40.01,6.35 v40.64,6.99 | v43.81,6.35 50.8,6.35 51.44,5.71 62.87,5.71 v64.14,6.99 | v66.04,33.66 66.67,34.29 70.48,34.29 71.75,35.56 v74.93,35.56 | v71.75,55.88 73.66,57.78 85.72,57.78 88.27,60.33 102.87,60.33 v103.5,59.69 | v106.68,76.2 105.41,74.93 102.87,74.93 101.6,73.66 101.6,68.58 4F.10 | v14.61,43.18 IC7.5
INTREQ\  (via drill 0.61)
  Top 0.254: v73.03,30.48 73.03,33.02 71.75,34.29 71.75,43.81 5E.4 | v93.98,29.21 93.98,31.75 v95.25,33.02 | v106.68,33.66 109.86,36.83 109.86,38.73 110.49,39.37 113.67,39.37 v113.67,64.77
  Bottom 0.254: v73.03,30.48 74.3,29.21 v93.98,29.21 | v95.25,33.02 96.52,34.29 106.05,34.29 v106.68,33.66 | v113.67,64.77 114.94,66.04 PL1.13
IOCLR\  (via drill 0.61)
  Top 0.254: v38.73,46.99 v38.73,77.47 | v10.16,85.09 10.16,101.6 IC6.1
  Bottom 0.254: v38.73,46.99 30.48,46.99 29.21,48.26 IC7.3 | 41.27,77.47 48.26,77.47 49.53,78.74 4C.20 | v38.73,77.47 41.27,77.47 | v10.16,85.09 12.06,83.19 35.56,83.19 41.27,77.47
IR3  (via drill 0.61)
  Top 0.254: v107.31,49.53 v107.31,45.72
  Bottom 0.254: v107.31,49.53 99.06,49.53 97.79,48.26 5F.12 | v107.31,45.72 6F.12
IR4  (via drill 0.61)
  Top 0.254: v106.68,107.31 106.68,100.33 106.05,99.69 106.05,87 107.95,85.09 107.95,71.75 106.68,70.48 106.68,52.07 106.05,51.44 106.05,42.55 6F.7 | v45.09,109.22 41.27,105.41 41.27,85.72 4C.3
  Bottom 0.254: v106.68,107.31 106.05,107.95 89.53,107.95 87,110.49 46.35,110.49 v45.09,109.22
IR5  (via drill 0.61)
  Top 0.254: v98.42,54.61 98.42,52.7 5F.13 | v107.95,54.61 109.22,53.34 109.22,42.55 108.58,41.91 109.86,40.64 6F.10
  Bottom 0.254: v98.42,54.61 v107.95,54.61
IR6  (via drill 0.61)
  Top 0.254: v40.01,72.39 40.01,75.56 4C.5 | 4B.15 52.07,25.4 v53.34,26.67 53.34,30.48 v50.16,33.66 | 6C.10 79.38,14.61 79.38,20.95 77.47,22.86 75.56,22.86 75.56,23.5 6C.2 | v30.48,72.39 30.48,50.8 29.21,49.53 29.84,48.9 v29.84,36.83
  Bottom 0.254: v40.01,72.39 v30.48,72.39 15.24,72.39 13.97,73.66 4A.3 | v53.34,26.67 68.58,26.67 69.85,25.4 6C.2 | v29.84,36.83 30.48,36.2 41.27,36.2 41.91,36.83 46.99,36.83 v50.16,33.66
IR7  (via drill 0.61)
  Top 0.254: v18.41,77.47 18.41,73.03 16.51,71.12 16.51,58.42 17.14,57.78 v17.14,2.54 | v45.72,3.17 43.81,5.08 46.99,8.26 46.99,13.97 4B.12
  Bottom 0.254: 4A.2 13.97,76.2 15.24,77.47 v18.41,77.47 37.47,77.47 38.73,76.2 4C.6 | 4B.12 55.88,17.78 57.15,19.05 71.12,19.05 72.39,20.32 6C.4 74.93,20.32 77.47,17.78 6C.12 | v17.14,2.54 17.78,3.17 v45.72,3.17
IR8  (via drill 0.61)
  Top 0.254: 55.88,8.89 59.69,5.08 77.47,5.08 77.47,10.16 78.74,11.43 | 55.88,8.89 52.07,12.7 4B.10 | 78.74,11.43 83.19,11.43 83.19,20.95 6C.14 | 78.74,11.43 78.74,20.32 77.47,20.32 75.56,18.41 75.56,17.14 6C.6 | v15.88,5.71 16.51,6.35 16.51,57.15 15.88,57.78 15.88,75.56 4A.1 | v45.09,5.08 55.88,5.08 55.88,8.89
  Bottom 0.254: 4A.1 10.79,76.83 10.79,74.93 40.01,74.93 41.27,73.66 4C.7 | v15.88,5.71 17.14,4.45 44.45,4.45 v45.09,5.08
IR9
  Top 0.254: 4B.7 45.72,15.24 45.72,69.85 44.45,71.12 4C.8
IR10
  Top 0.254: 4B.5 40.64,20.32 40.64,66.04 4C.9
IR11  (via drill 0.61)
  Top 0.254: v46.99,25.4 46.35,26.04 46.35,48.9 48.26,50.8 v48.26,66.04
  Bottom 0.254: 4B.2 v46.99,25.4 | v48.26,66.04 4C.10
LOADIF  (via drill 0.61)
  Top 0.254: 69.22,77.47 69.22,87 69.85,87.63 69.85,97.79 72.39,100.33 75.56,100.33 75.56,93.34 3E.6 | 69.22,77.47 69.22,74.93 69.85,74.3 69.85,64.77 4D.9 | 69.22,77.47 v69.85,77.47 | v114.94,84.45 v114.94,96.52 | 4F.1 v88.9,85.72
  Bottom 0.254: v69.85,77.47 86.36,77.47 87.63,78.74 4F.1 | v114.94,84.45 107.95,84.45 106.68,85.72 v88.9,85.72 | v114.94,96.52 IC1.11
LOADIR  (via drill 0.61)
  Top 0.254: v54.61,7.62 52.07,10.16 4B.9 | v105.41,6.35 109.22,10.16 v109.22,21.59 109.22,34.92 111.12,36.83 111.12,37.47 6F.9 | v131.44,27.94 v131.44,86.36
  Bottom 0.254: v54.61,7.62 55.24,8.26 66.67,8.26 68.58,6.35 v105.41,6.35 | v131.44,86.36 122.56,95.25 99.06,95.25 97.79,96.52 3F.11 | v131.44,27.94 123.83,20.32 114.3,20.32 113.03,21.59 v109.22,21.59
MEMSEL\  (via drill 0.61)
  Top 0.254: v92.71,72.39 v92.71,76.2
  Bottom 0.254: v92.71,72.39 83.82,72.39 82.55,73.66 4E.12 | v92.71,76.2 93.98,77.47 122.56,77.47 123.83,78.74 PL1.4
N$1
  Top 0.254: 3B.11 34.92,97.16 34.92,98.42 3B.12
N$2
  Bottom 0.254: 3B.6 3B.9
N$3
  Top 0.254: 3B.8 40.01,93.34 40.01,106.68 45.72,112.39 87,112.39 87,103.5 3F.2 87,99.69 87,75.56 4F.3
N$4  (via drill 0.61)
  Top 0.254: v60.33,92.71 60.96,92.08 60.96,73.03 60.33,72.39 60.33,71.12 v61.59,69.85
  Bottom 0.254: 76.2,69.85 74.93,68.58 4E.5 | 76.2,69.85 82.55,69.85 83.82,68.58 4F.5 | v60.33,92.71 57.15,92.71 55.88,93.98 3B.10 | v61.59,69.85 76.2,69.85
N$5  (via drill 0.61)
  Top 0.254: 5E.1 74.93,53.34 76.2,54.61 v76.2,64.77 76.2,65.41 77.47,66.67 77.47,88.27 78.11,88.9 78.11,91.44 76.2,93.34 76.2,105.41 71.12,105.41 67.31,101.6 3D.13
  Bottom 0.254: v76.2,64.77 85.72,64.77 87,66.04 4F.6
N$6
  Bottom 0.254: 3D.5 59.69,93.98 60.96,95.25 71.12,95.25 72.39,96.52 3E.4
N$7  (via drill 0.61)
  Top 0.254: v78.11,43.18 v78.11,62.23 | v71.75,62.23 v71.75,85.72 | v85.09,85.72 85.72,86.36 85.72,100.97 85.09,101.6 v85.09,104.14 | v53.34,95.25 54.61,93.98 v54.61,86.36
  Bottom 0.254: v78.11,62.23 v71.75,62.23 | v85.09,85.72 v71.75,85.72 71.12,85.09 56.52,85.09 55.88,85.72 55.24,85.72 v54.61,86.36 | v78.11,43.18 5E.10 | v85.09,104.14 3F.1 | v53.34,95.25 47.62,95.25 46.35,96.52 R1.1
N$8  (via drill 0.61)
  Top 0.254: v86.36,57.15 86.36,50.8 5E.11 | v95.25,57.78 95.89,58.42 95.89,62.87 4F.8 98.42,65.41 98.42,97.16 3F.12
  Bottom 0.254: v86.36,57.15 87,57.78 v95.25,57.78
N$9  (via drill 0.61)
  Top 0.254: v92.08,52.07 92.08,65.41 v92.71,66.04 | v56.52,52.07 56.52,57.78 55.88,58.42 55.88,66.04 53.98,67.94 53.98,77.47 49.53,77.47 48.26,78.74 R2.1
  Bottom 0.254: 76.2,52.07 74.93,50.8 5E.2 | 76.2,52.07 v92.08,52.07 | v92.71,66.04 4F.9 | v56.52,52.07 76.2,52.07
N$10  (via drill 0.61)
  Top 0.254: v68.58,87.63 v68.58,66.04
  Bottom 0.254: v68.58,87.63 45.72,87.63 44.45,88.9 4C.1 | v68.58,66.04 4E.6 75.56,66.04 76.83,67.31 90.17,67.31 91.44,68.58 92.71,68.58 92.71,69.85 91.44,71.12 4F.4
N$11  (via drill 0.61)
  Top 0.254: v61.59,72.39 62.23,73.03 62.23,97.79 60.96,99.06 3D.3
  Bottom 0.254: v61.59,72.39 71.12,72.39 72.39,71.12 4E.4
N$12  (via drill 0.61)
  Top 0.254: v60.96,97.79 59.69,96.52 3D.4
  Bottom 0.254: v60.96,97.79 83.19,97.79 84.45,99.06 3F.3
N$13  (via drill 0.61)
  Top 0.254: v84.45,97.79 84.45,102.87 83.82,103.5 83.82,111.76 46.35,111.76 40.64,106.05 40.64,87.63 34.29,87.63 33.66,88.27 33.66,99.69 34.29,100.33 33.66,100.97 33.66,105.41 32.38,105.41 31.11,104.14 31.11,75.56 IC4.11 | v113.67,97.79 v113.67,74.93
  Bottom 0.254: v84.45,97.79 v113.67,97.79 | v113.67,74.93 106.68,74.93 105.41,73.66 IC3.3
N$14  (via drill 0.61)
  Top 0.254: v84.45,76.2 83.82,76.83 v83.82,95.25
  Bottom 0.254: v83.82,95.25 93.98,95.25 95.25,93.98 3F.10 | 4E.13 v84.45,76.2
N$15  (via drill 0.61)
  Top 0.254: v17.78,62.23 17.78,5.71 18.41,5.08 18.41,1.27 80.01,1.27 81.92,3.17 99.69,3.17 106.05,9.53 106.05,13.34 6E.6
  Bottom 0.254: v17.78,62.23 29.21,62.23 29.84,61.59 41.27,61.59 41.91,62.23 46.99,62.23 49.53,64.77 60.96,64.77 63.5,67.31 75.56,67.31 76.83,68.58 4E.10
N$16  (via drill 0.61)
  Top 0.254: v99.69,73.66 101.6,75.56 101.6,101.6 IC1.1
  Bottom 0.254: 4F.12 v99.69,73.66 | SV1.3 115.57,104.14 114.3,102.87 106.68,102.87 105.41,104.14 IC1.1
N$17  (via drill 0.61)
  Top 0.254: v88.9,1.91 99.69,1.91 106.68,8.89 106.68,13.97 106.05,14.61 106.05,23.5 6E.2 | v15.88,3.81 14.61,5.08 14.61,5.71 15.88,6.99 15.88,56.52 v15.24,57.15 | v41.91,57.78 41.27,58.42 41.27,64.14 41.91,64.77 45.09,64.77 45.09,69.22 44.45,69.85 41.27,69.85 v41.27,74.93 | v70.48,74.93 71.12,75.56 71.12,78.11 v70.48,78.74
  Bottom 0.254: v88.9,1.91 85.72,5.08 46.35,5.08 45.09,3.81 v15.88,3.81 | v15.24,57.15 15.88,57.78 v41.91,57.78 | v41.27,74.93 v70.48,74.93 | v70.48,78.74 4E.1
N$18  (via drill 0.61)
  Top 0.254: v100.33,44.45 100.97,45.09 v100.97,48.26 | v93.98,49.53 93.98,57.78 94.61,58.42 94.61,80.01 95.89,80.01 96.52,80.64 3F.8 | v93.98,46.99 94.61,46.35 94.61,45.09 5F.10
  Bottom 0.254: v100.33,44.45 99.06,44.45 97.79,43.18 5F.10 | v100.97,48.26 6F.4 | v93.98,46.99 v93.98,49.53
N$19  (via drill 0.61)
  Top 0.254: v106.68,36.83 107.95,38.1 107.95,42.55 108.58,43.18 108.58,50.16 v107.95,50.8
  Bottom 0.254: v106.68,36.83 99.06,36.83 97.79,38.1 5F.8 | v107.95,50.8 6F.14
N$20  (via drill 0.61)
  Top 0.254: v46.99,50.8 46.35,51.44 46.35,78.11 4C.4 | v61.59,49.53 62.87,48.26 62.87,38.73 64.14,37.47 v64.14,34.29 | v80.01,32.38 80.64,33.02 v80.64,34.92 | v89.53,36.2 92.08,38.73 v92.08,45.09
  Bottom 0.254: v46.99,50.8 48.26,49.53 v61.59,49.53 | v64.14,34.29 66.04,32.38 v80.01,32.38 | v80.64,34.92 81.92,36.2 v89.53,36.2 | v92.08,45.09 92.71,45.72 5F.11
N$24
  Bottom 0.254: IC1.13 SV1.2
N$25  (via drill 0.61)
  Top 0.254: v24.77,73.66 v24.77,90.81 | v42.55,92.71 44.45,94.61 44.45,107.31 48.26,111.12 76.83,111.12 76.83,101.6 78.74,99.69 78.74,88.27 78.11,87.63 78.11,86.36 v80.64,83.82 | v103.5,83.82 103.5,79.38 IC3.1
  Bottom 0.254: v24.77,90.81 26.67,92.71 v42.55,92.71 | v80.64,83.82 81.28,83.19 99.06,83.19 99.69,83.82 v103.5,83.82 | v24.77,73.66 IC4.3
N$26  (via drill 0.61)
  Top 0.254: v47.62,22.86 47.62,15.88 45.09,13.34 45.09,7.62 41.27,7.62 40.01,8.89 34.29,8.89 32.38,10.79 32.38,15.88 31.11,15.88 29.84,14.61 29.84,13.97 26.67,13.97 25.4,15.24 25.4,38.1 IC7.6 | v76.2,24.13 77.47,25.4 77.47,41.27 79.38,43.18 79.38,54.61 78.74,55.24 78.74,61.59 v79.38,62.23
  Bottom 0.254: v47.62,22.86 48.9,24.13 v76.2,24.13 | v79.38,62.23 84.45,62.23 87,64.77 90.17,64.77 94.61,69.22 94.61,72.39 99.69,72.39 100.97,73.66 100.97,76.2 4F.13
N$45  (via drill 0.61)
  Top 0.254: 5D.2 60.96,53.34 60.96,60.96 4D.7 | v87,33.02 87,27.3 6D.2 | v71.12,33.66 v71.12,49.53
  Bottom 0.254: v87,33.02 86.36,33.66 v71.12,33.66 | v71.12,49.53 62.87,49.53 61.59,50.8 5D.2
N$46  (via drill 0.61)
  Top 0.254: 5D.11 63.5,43.18 63.5,73.66 4D.15 | v84.45,40.64 84.45,18.41 87.63,15.24 6D.6
  Bottom 0.254: v84.45,40.64 83.19,41.91 69.22,41.91 67.94,40.64 5D.11
N$47  (via drill 0.61)
  Top 0.254: v61.59,43.18 60.96,43.81 60.96,48.9 60.33,49.53 60.33,51.44 62.23,53.34 v62.23,63.5 | v77.47,19.05 76.2,17.78 76.2,15.24 74.93,13.97 71.12,13.97 v71.12,27.94 | v54.61,34.29 v54.61,43.18
  Bottom 0.254: v61.59,43.18 5D.5 v54.61,43.18 | v62.23,63.5 4D.10 | v77.47,19.05 86.36,19.05 87.63,20.32 6D.4 | v71.12,27.94 69.85,29.21 62.87,29.21 57.78,34.29 v54.61,34.29
N$48  (via drill 0.61)
  Top 0.254: v66.67,81.28 66.67,88.27 3D.8 | 5B.1 v12.7,43.18 | v8.89,86.36 8.26,85.72 v8.26,51.44
  Bottom 0.254: v66.67,81.28 65.41,80.01 60.96,80.01 59.69,78.74 4D.1 57.15,78.74 55.88,80.01 40.01,80.01 35.56,84.45 12.06,84.45 10.16,86.36 v8.89,86.36 | 14.61,45.09 21.59,52.07 40.64,52.07 41.91,53.34 5C.1 | v12.7,43.18 14.61,45.09 | 14.61,45.09 v8.26,51.44
N$50  (via drill 0.61)
  Top 0.254: v30.48,49.53 30.48,44.45 31.11,43.81 31.11,28.57 IC2.3 | v54.61,66.04 53.98,65.41 v53.98,53.98
  Bottom 0.254: v30.48,49.53 40.64,49.53 41.91,50.8 5C.2 44.45,50.8 45.72,52.07 52.07,52.07 v53.98,53.98 | v54.61,66.04 57.15,68.58 4D.5
N$51  (via drill 0.61)
  Top 0.254: v38.73,24.13 40.01,25.4 40.01,36.83 | 40.01,36.83 v39.37,37.47 | 40.01,36.83 v40.01,69.85
  Bottom 0.254: v38.73,24.13 30.48,24.13 29.21,22.86 IC2.4 | v39.37,37.47 40.01,38.1 5C.7 | v40.01,69.85 59.69,69.85 60.96,68.58 4D.12
N$52  (via drill 0.61)
  Top 0.254: v33.02,30.48 33.02,20.32 IC2.7 | v48.9,33.66 48.9,36.2 5C.10 | v64.77,57.78 64.14,58.42 64.14,69.22 4D.13 | v55.24,57.78 55.24,48.9 53.34,46.99 v53.34,36.83
  Bottom 0.254: v33.02,30.48 34.29,31.75 39.37,31.75 41.27,33.66 v48.9,33.66 | v55.24,57.78 v64.77,57.78 | v53.34,36.83 52.07,38.1 5C.10
N$53  (via drill 0.61)
  Top 0.254: v24.13,26.67 24.13,15.24 26.67,12.7 IC2.8 | 5D.3 56.52,46.35 56.52,27.3 6B.2
  Bottom 0.254: 5B.2 13.97,25.4 15.24,26.67 v24.13,26.67 52.07,26.67 53.34,25.4 6B.2
N$54  (via drill 0.61)
  Top 0.254: v48.26,12.7 48.26,13.97 52.07,13.97 6B.4 | v38.73,29.84 37.47,28.57 37.47,14.61 IC2.13
  Bottom 0.254: 5B.7 13.97,12.7 15.24,13.97 30.48,13.97 31.75,12.7 IC2.13 37.47,12.7 38.73,11.43 44.45,11.43 45.09,12.06 47.62,12.06 v48.26,12.7 | v38.73,29.84 40.64,31.75 49.53,31.75 5D.6
N$55  (via drill 0.61)
  Top 0.254: v30.48,8.89 31.11,9.53 v31.11,14.61 | v62.23,38.1 61.59,37.47 v61.59,15.24
  Bottom 0.254: v30.48,8.89 25.4,8.89 21.59,12.7 5B.10 | v31.11,14.61 31.75,15.24 IC2.14 38.73,15.24 40.01,16.51 52.07,16.51 53.34,15.24 6B.6 v61.59,15.24 | v62.23,38.1 5D.10
N$59  (via drill 0.61)
  Top 0.254: v21.59,7.62 21.59,6.35 29.21,6.35 29.84,6.99 29.84,7.62 IC2.11 | v46.99,107.95 46.99,74.3 v48.9,72.39 | v61.59,71.12 62.87,72.39 62.87,75.56 64.77,77.47 67.94,77.47 67.94,87 67.31,87.63 67.94,88.27 67.94,89.53 3D.9
  Bottom 0.254: v21.59,7.62 20.32,8.89 8.26,8.89 6.99,10.16 4.45,10.16 1.91,12.7 1.91,104.14 10.16,104.14 13.97,107.95 v46.99,107.95 | v48.9,72.39 60.33,72.39 v61.59,71.12
N$70  (via drill 0.61)
  Top 0.254: v79.38,102.87 79.38,90.81 3E.8
  Bottom 0.254: v79.38,102.87 78.11,104.14 3E.1
N$71  (via drill 0.61)
  Top 0.254: v86.36,101.6 86.36,72.39 90.17,72.39 90.81,73.03 90.81,74.3 4F.2
  Bottom 0.254: v86.36,101.6 3E.13
N$72
  Top 0.254: 3B.3 27.3,99.69 27.3,100.97 3B.2
N$74
  Bottom 0.254: 3B.4 29.21,96.52 30.48,97.79 59.69,97.79 60.96,96.52 3D.11
POPR
  Top 0.254: IC7.8 33.66,40.01 33.66,48.9 IC7.13
RDF\  (via drill 0.61)
  Top 0.254: v62.87,6.99 v62.87,25.4 | v40.64,5.71 20.32,5.71 v20.32,7.62 | v12.7,7.62 10.79,9.53 v10.79,67.31 | v17.78,67.31 18.41,67.94 18.41,71.75 4A.14
  Bottom 0.254: v62.87,6.99 62.23,6.35 52.07,6.35 50.8,7.62 42.55,7.62 v40.64,5.71 | v12.7,7.62 v20.32,7.62 | v10.79,67.31 v17.78,67.31 | v62.87,25.4 6B.15
RIF\  (via drill 0.61)
  Top 0.254: v68.58,60.33 v68.58,50.8 | v93.34,43.81 93.34,29.84 92.71,29.21 92.71,27.94 95.25,25.4 6D.15
  Bottom 0.254: v68.58,60.33 67.94,59.69 41.91,59.69 41.27,60.33 31.75,60.33 31.11,59.69 19.05,59.69 16.51,62.23 9.53,62.23 9.53,67.94 11.43,69.85 13.97,69.85 14.61,70.48 18.41,70.48 19.05,71.12 4A.13 | v68.58,50.8 71.12,50.8 72.39,49.53 82.55,49.53 87.63,44.45 91.44,44.45 92.08,43.81 v93.34,43.81
RMEN\  (via drill 0.61)
  Top 0.254: 5E.9 83.19,38.73 v83.19,26.67 83.82,26.04 83.82,7.62 v80.01,3.81 | v23.5,85.72 22.23,84.45 22.23,51.44 22.86,50.8 22.86,20.32 21.59,19.05 18.41,19.05 18.41,6.35 22.86,1.91 77.47,1.91 v77.47,2.54
  Bottom 0.254: v83.19,26.67 101.6,26.67 102.87,27.94 6E.1 | v23.5,85.72 38.73,85.72 40.64,87.63 44.45,87.63 45.09,87 48.9,87 49.53,86.36 4C.23 | v77.47,2.54 78.74,3.81 v80.01,3.81
RMF\  (via drill 0.61)
  Top 0.254: v14.61,64.77 14.61,74.3 13.97,74.93 10.79,74.93 10.79,79.38 11.43,80.01 15.24,80.01 v15.24,109.22 | v102.23,110.49 106.05,106.68 106.05,100.97 IC1.3
  Bottom 0.254: v14.61,64.77 17.78,64.77 19.05,66.04 4A.11 | v15.24,109.22 19.05,113.03 99.69,113.03 v102.23,110.49
RUN  (via drill 0.61)
  Top 0.254: 37.47,71.75 37.47,42.55 IC7.9 | 37.47,71.75 IC4.12 | v128.27,95.89 128.27,69.85 123.83,69.85 122.56,68.58 PL1.11 | v71.12,104.14 68.58,101.6 v68.58,99.69 | v33.02,100.33 33.02,84.45 37.47,80.01 37.47,71.75
  Bottom 0.254: v128.27,95.89 118.11,106.05 96.52,106.05 95.89,105.41 72.39,105.41 v71.12,104.14 | v68.58,99.69 67.94,100.33 v33.02,100.33
RUNHLT\
  Bottom 0.254: IC3.4 105.41,71.12 106.68,69.85 122.56,69.85 123.83,68.58 PL1.12
SELIR\  (via drill 0.61)
  Top 0.254: v69.85,26.67 69.85,34.92 70.48,35.56 70.48,48.9 69.85,49.53 v69.85,60.33
  Bottom 0.254: v69.85,26.67 78.74,26.67 80.01,25.4 6C.15 | v69.85,60.33 67.94,62.23 53.34,62.23 52.07,63.5 4C.14
SINT\  (via drill 0.61)
  Top 0.254: v23.5,66.67 v23.5,76.2
  Bottom 0.254: 4A.10 v23.5,66.67 | v23.5,76.2 IC4.2
SKP\  (via drill 0.61)
  Top 0.254: v106.05,72.39 106.05,74.3 IC3.2
  Bottom 0.254: v106.05,72.39 122.56,72.39 123.83,71.12 PL1.10
SUF\  (via drill 0.61)
  Top 0.254: v14.61,59.69 14.61,61.59 4A.7 | v100.33,96.52 99.69,97.16 v99.69,99.69
  Bottom 0.254: v14.61,59.69 6.99,59.69 2.54,64.14 2.54,97.79 21.59,97.79 26.67,102.87 52.07,102.87 52.7,103.5 56.52,103.5 57.15,102.87 68.58,102.87 69.85,101.6 3E.2 76.83,101.6 78.11,100.33 99.06,100.33 v99.69,99.69 | v100.33,96.52 IC1.4
SWSEL\  (via drill 0.61)
  Top 0.254: v99.06,50.8 99.06,49.53 95.25,49.53 90.81,45.09 90.81,42.55 5F.6
  Bottom 0.254: v99.06,50.8 100.33,52.07 107.95,52.07 110.49,54.61 114.3,54.61 116.2,56.52 120.65,56.52 121.28,57.15 128.91,57.15 130.18,58.42 130.18,69.85 123.83,69.85 122.56,71.12 PL1.9
UB  (via drill 0.61)
  Top 0.254: v107.31,93.98 107.31,102.23 110.49,105.41 113.67,105.41 113.67,100.97 IC1.12
  Bottom 0.254: IC1.5 v107.31,93.98
UB\  (via drill 0.61)
  Top 0.254: v99.69,74.93 100.97,76.2 100.97,90.81 v100.33,91.44
  Bottom 0.254: v99.69,74.93 76.2,74.93 74.93,73.66 4E.3 | v100.33,91.44 IC1.6
UIF\  (via drill 0.61)
  Top 0.254: v69.22,43.18 v69.22,48.26 | v9.53,41.91 9.53,83.19 11.43,85.09 11.43,87.63 10.79,88.27 10.79,89.53 IC6.6
  Bottom 0.254: IC6.6 11.43,91.44 7.62,87.63 7.62,82.55 34.92,82.55 35.56,81.92 35.56,80.01 31.75,80.01 30.48,78.74 IC4.1 | v69.22,43.18 67.94,41.91 v9.53,41.91 | v69.22,48.26 5E.3
USER_MODE  (via drill 0.61)
  Top 0.254: IC7.2 27.3,51.44 27.3,52.7 IC7.1 26.04,55.24 26.04,64.14 26.67,64.77 29.84,64.77 29.84,71.75 29.21,72.39 30.48,73.66 30.48,104.78 v37.47,111.76 | 5F.4 90.81,47.62 90.81,48.9 5F.2 | v109.86,64.77 109.86,89.53 IC1.9 | v100.97,64.77 99.69,63.5 v99.69,53.34 | v92.08,110.49 v92.08,92.08
  Bottom 0.254: v109.86,64.77 v100.97,64.77 | v99.69,53.34 98.42,52.07 93.34,52.07 92.08,50.8 5F.2 | v37.47,111.76 90.81,111.76 v92.08,110.49 | v92.08,92.08 92.71,92.71 109.22,92.71 110.49,91.44 IC1.9
USER_MODE\  (via drill 0.61)
  Top 0.254: v32.38,104.14 31.75,103.5 31.75,80.01 IC4.13 | v81.28,108.58 83.19,106.68 v83.19,102.87 | v108.58,99.69 v108.58,88.9
  Bottom 0.254: v32.38,104.14 33.66,105.41 56.52,105.41 59.05,107.95 78.11,107.95 78.74,108.58 v81.28,108.58 | v83.19,102.87 105.41,102.87 v108.58,99.69 | v108.58,88.9 IC1.8
VCC  (via drill 0.61)
  Top 0.254: IC1.10 109.86,95.89 109.86,102.23 IC1.14 | 94.61,104.14 94.61,106.68 C6.1 | 94.61,104.14 94.61,82.55 95.25,81.92 C12.1 | 94.61,104.14 3F.14 | 4E.14 80.01,80.01 C11.1 | 4A.16 19.68,79.38 19.68,80.01 19.05,80.64 C7.1 19.05,81.92 18.41,82.55 18.41,102.23 IC6.14 | IC4.14 34.29,80.01 C8.1 | 4D.16 64.77,80.01 C10.1 64.14,81.28 64.14,92.08 | 64.14,92.08 3D.10 | 64.14,92.08 64.14,97.16 3D.12 64.14,100.97 64.14,106.68 C4.1 64.77,106.05 65.41,105.41 65.41,104.78 3D.14 | C5.1 80.01,105.41 3E.14 78.11,104.14 v78.11,102.87 | 4C.24 49.53,90.17 C9.1 49.53,92.08 52.07,94.61 52.07,102.23 | 3B.14 34.29,105.41 C3.1 | 52.07,102.23 48.26,106.05 R2.2 | 52.07,102.23 55.24,99.06 55.24,89.53 57.78,87 57.78,81.28 56.52,80.01 56.52,73.03 4D.4 | IC7.14 34.29,54.61 C14.1 | v17.78,66.04 18.41,65.41 18.41,62.87 19.05,62.23 18.41,61.59 18.41,55.88 C13.1 v19.05,35.56 C19.1 18.41,30.48 18.41,27.94 | 5F.14 95.25,54.61 C18.1 | 6F.3 106.05,52.7 106.05,53.98 6F.1 | C17.1 80.01,55.24 80.64,54.61 80.64,53.98 5E.14 | C16.1 64.77,55.24 65.41,54.61 65.41,53.98 5D.16 | 48.9,53.34 48.9,55.88 C15.1 | 48.9,53.34 48.9,47.62 5C.13 | 5C.16 48.9,53.34 | C22.1 64.77,29.84 65.41,29.21 65.41,28.57 6B.16 | C23.1 80.01,29.84 80.64,29.21 80.64,28.57 6C.16 | C24.1 95.25,29.84 95.89,29.21 95.89,28.57 6D.16 | v123.83,29.21 123.83,31.75 124.46,32.38 PL1.40 | IC2.20 34.29,31.75 C20.1 | C21.1 49.53,29.84 50.16,29.21 50.16,28.57 4B.16 | 18.41,27.94 18.41,22.23 5B.13 | 18.41,27.94 5B.16 | v5.71,74.3 5.71,36.83 C1.+
  Bottom 0.254: IC1.14 110.49,104.14 109.22,105.41 99.06,105.41 97.79,104.14 3F.14 | 121.28,81.28 120.02,80.01 116.2,80.01 114.94,78.74 IC3.14 110.49,78.74 109.22,80.01 99.06,80.01 97.79,78.74 4F.14 94.61,78.74 93.34,80.01 83.82,80.01 82.55,78.74 4E.14 76.2,78.74 74.93,80.01 68.58,80.01 67.31,78.74 4D.16 | 121.28,81.28 C12.1 | 121.28,81.28 PL1.1 | 4A.16 21.59,78.74 22.86,80.01 30.48,80.01 31.75,81.28 C8.1 | C2.+ 5.71,102.87 17.78,102.87 19.05,104.14 IC6.14 21.59,104.14 22.86,105.41 32.38,105.41 33.66,106.68 C3.1 R1.2 R2.2 | v78.11,102.87 69.85,102.87 68.58,104.14 3D.14 3D.1 3B.14 | C13.1 19.68,55.88 20.95,57.15 32.38,57.15 33.66,55.88 C14.1 | v17.78,66.04 4A.6 | 6F.16 6F.1 C18.1 94.61,55.88 93.34,57.15 87.63,57.15 86.36,55.88 C17.1 | 53.34,54.61 52.07,53.34 5C.16 | 53.34,54.61 55.88,57.15 62.87,57.15 64.14,55.88 C16.1 | 5E.14 80.01,53.34 79.38,53.98 75.56,53.98 74.93,54.61 70.48,54.61 69.22,53.34 5D.16 | 53.34,54.61 38.1,54.61 36.83,53.34 IC7.14 | C22.1 65.41,30.48 66.67,31.75 78.11,31.75 79.38,30.48 C23.1 80.64,30.48 81.92,31.75 93.34,31.75 94.61,30.48 C24.1 | 6D.16 101.6,27.94 102.87,29.21 109.22,29.21 110.49,27.94 6E.16 122.56,27.94 v123.83,29.21 | v19.05,35.56 C1.+ | 5B.16 21.59,27.94 22.86,29.21 33.02,29.21 34.29,30.48 IC2.20 36.83,30.48 39.37,27.94 4B.1 4B.16 52.07,27.94 53.34,29.21 59.69,29.21 60.33,28.57 64.14,28.57 64.77,27.94 6B.16 | v5.71,74.3 11.43,80.01 17.14,80.01 18.41,81.28 C7.1
XTA  (via drill 0.61)
  Top 0.254: v99.69,82.55 99.06,83.19 99.06,99.06 3F.13
  Bottom 0.254: v99.69,82.55 125.09,82.55 125.73,81.92 125.73,76.83 124.46,76.83 PL1.6
XTC  (via drill 0.61)
  Top 0.254: v26.04,109.22 26.04,95.89 3B.5 | v113.03,108.58 114.94,106.68 114.94,100.33 122.56,100.33 122.56,96.52 127,92.08 127,79.38 125.09,77.47 121.92,77.47 PL1.5
  Bottom 0.254: v26.04,109.22 27.3,110.49 45.09,110.49 45.72,111.12 90.17,111.12 92.71,108.58 v113.03,108.58

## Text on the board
Bottom: EMC6907 MMU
